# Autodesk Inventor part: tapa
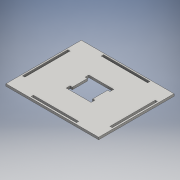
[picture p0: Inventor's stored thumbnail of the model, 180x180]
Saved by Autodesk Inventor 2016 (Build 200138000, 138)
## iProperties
Created: 2016-06
Part Number: tapa
Material: Genérico
Document SubType Name: Modeling
Designer: adm
Density: 1 g/cm^3
Appearance: Valor por defecto
Author: adm
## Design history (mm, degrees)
sketch "Boceto1"
  geometry: L1 (-61, -30)-(-58, -30); L2 (-31.5, -45)-(-31.5, -48); L3 (-61, -30)-(-61, 30); L4 (-61, 30)-(-58, 30); L5 (-58, 30)-(-58, -30); L6 (-31.5, -45)-(28.5, -45); L7 (28.5, -45)-(28.5, -48); L8 (28.5, -48)-(-31.5, -48); L9 (-31.5, 48)-(-31.5, 45); L10 (-63, 50)-(-63, -50); L11 (-63, -50)-(60, -50); L12 (30, 45)-(-31.5, 45); L13 (-31.5, 48)-(30, 48); L14 (-63, -50)-(60, 50); L15 (60, 50)-(-63, 50); L16 (60, -50)-(-63, 50); L17 (60, -50)-(60, 50); L18 (30, 48)-(30, 45); L19 (55, -30)-(55, 30); L20 (55, 30)-(58, 30); L21 (58, 30)-(58, -30); L22 (55, -30)-(58, -30); L23 (-18, 15)-(15, 15); L24 (15, -15)-(-18, -15); L25 (-18, 15)-(15, -15); L26 (15, 15)-(-18, -15); L27 (-15, 10)-(-15, -10); L28 (12, -10)-(12, 10); L29 (-18, -15)-(-18, -10); L30 (-18, 10)-(-18, 15); L31 (15, 15)-(15, 10); L32 (15, -10)-(15, -15); L33 (15, 10)-(12, 10); L34 (-15, 10)-(-18, 10); L35 (-18, -10)-(-15, -10); L36 (12, -10)-(15, -10); 2 further points
  constraints: 72 end point, 16 parallel, 7 perpendicular, 4 midpoint, 2 horizontal
  dimensions: "d0" = 100 distance of L14.end L11.end; "d1" = 123 distance of L14.end L10.start; "d2" = 33 distance of L24.start L24.end; "d3" = 30 distance of L23.end L24.start; "d7" = 5 distance between parallel lines of L34 L23; "d8" = 5 distance between parallel lines of L33 L23; "d9" = 5 distance between parallel lines of L24 L36; "d10" = 5 distance between parallel lines of L35 L24; "d11" = 31.5 distance between parallel lines of L2 L10; "d12" = 20 distance between parallel lines of L11 L1; "d13" = 2 distance between parallel lines of L3 L10; "d14" = 3 distance of L3.end L4.end; "d15" = 2 distance between parallel lines of L21 L17; "d17" = 3 distance between parallel lines of L19 L21; "d19" = 31.5 distance between parallel lines of L10 L9
extrude "Extrusión1" new body sketch "Boceto1" distance "d5" = 3; taper "d6" = 0 deg
node "Sólido1"
other parameters: "d4" = 3
